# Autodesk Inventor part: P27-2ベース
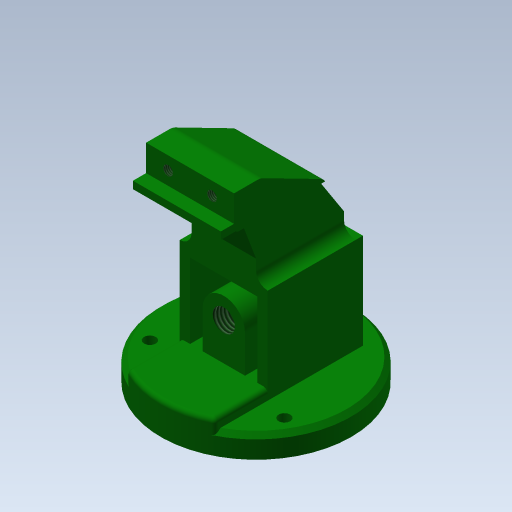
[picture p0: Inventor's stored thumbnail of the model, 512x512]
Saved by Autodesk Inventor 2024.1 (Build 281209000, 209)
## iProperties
Created: 2008-07
Part Number: P27-2ベース
Document SubType Name: Modeling
Designer: y-shimohigashi
Density: 1 g/cm^3
Stock Number: P24-2ベース
Material: 一般
Appearance: 濃い緑
Author: y-shimohigashi
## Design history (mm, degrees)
sketch "スケッチ2"
  geometry: C1 r 65 at (0, 0); 1 further point
  constraints: 1 centre point, 1 coincident
  dimensions: "d0" = 130 diameter of C1
extrude "押し出し1" new body sketch "スケッチ2" distance "d1" = 15; taper "d2" = 0 deg
sketch "スケッチ3"
  geometry: L1 (-65, 15)-(65, 15) reference; L2 (43, 15)-(43, 80); L3 (43, 80)-(38, 80); L4 (38, 80)-(38, 93); L5 (38, 93)-(16, 127); L6 (16, 127)-(-27, 149); L7 (-27, 149)-(-45, 149); L8 (-45, 149)-(-45, 131); L9 (-45, 131)-(-54, 131); L10 (-54, 131)-(-54, 126); L11 (-54, 126)-(-44, 126); L12 (-44, 126)-(-31, 119); L13 (-31, 119)-(-22, 95); L14 (-22, 95)-(-22, 15); L15 (-22, 15)-(43, 15); 1 further point
  constraints: 28 end point, 6 parallel, 3 perpendicular, 2 point on line, 1 collinear
  dimensions: "d3" = 43 distance from line of L2 point (0, 0); "d4" = 65 distance of L2.start L2.end; "d5" = 13 distance of L3.end L4.end; "d6" = 34 vertical distance of L4.end L5.end; "d7" = 22 vertical distance of L5.end L6.end; "d8" = 5 distance of L2.end L3.end; "d9" = 22 horizontal distance of L4.end L5.end; "d10" = 43 horizontal distance of L5.end L6.end; "d11" = 18 distance of L6.end L7.end; "d12" = 9 distance of L8.end L9.end; "d13" = 18 distance of L7.end L8.end; "d14" = 5 distance of L9.end L10.end; "d15" = 10 distance of L10.end L11.end; "d16" = 24 vertical distance of L12.end L13.end; "d17" = 80 distance of L13.end L14.end; "d18" = 65 distance between parallel lines of L2 L14; "d19" = 13 horizontal distance of L11.end L12.end
extrude "押し出し2" join sketch "スケッチ3" stored distance "d20" = 60; taper "d21" = 0 deg
sketch "スケッチ4"
  geometry: L1 (0, 0)-(60, 0) reference; L2 (60, 0)-(52, 0); L3 (52, 0)-(52, -45); L4 (52, -45)-(60, -45); L5 (60, -45)-(60, 0); L6 (0, 0)-(8, 0); L7 (8, 0)-(8, -45); L8 (8, -45)-(0, -45); L9 (0, -45)-(0, 0)
  constraints: 16 end point, 4 parallel, 2 collinear, 2 horizontal, 2 perpendicular
  dimensions: "d22" = 8 distance of L3.end L4.end; "d23" = 45 distance of L4.end L1.end
extrude "押し出し3" cut sketch "スケッチ4" extent not by distance; stored distance "d24" = 60; taper "d25" = 0 deg
sketch "スケッチ5"
  geometry: L1 (60, -65)-(60, 0) reference; L2 (0, 0)-(60, 0) reference; L3 (0, 0)-(0, -65) reference; L4 (0, -65)-(60, -65) reference; L5 (53, -58)-(53, -7); L6 (53, -7)-(7, -7); L7 (7, -7)-(7, -58); L8 (7, -58)-(53, -58); L9 (44.5, -7)-(44.5, -32.5); L10 (15.5, -32.5)-(15.5, -7); A1 r 14.5 centre (30, -32.5) between (15.5, -32.5) and (44.5, -32.5); 2 further points
  constraints: 12 end point, 2 midpoint, 2 perpendicular, 2 point on circle, 2 point on line, 2 tangent, 1 centre point, 1 horizontal alignment, 1 vertical alignment, 3 other
  dimensions: "d26" = 7 distance between parallel lines of L3 L7; "d27" = 8.5 distance between parallel lines of L7 L10
extrude "押し出し4" cut sketch "スケッチ5" extent not by distance; stored distance "d28" = 60; taper "d29" = 0 deg
hole "穴1" diameter "d32" = 15.294; stored, may be unused: countersink angle "d36" = 90 deg, drill point angle "d38" = 118 deg; dims "d30" = 10, "d31" = 10, "d33" = 6, "d34" = 4, "d35" = 2, "d37" = 8
sketch "スケッチ6"
  geometry: L1 (30, -22)-(-30, -22) reference; L2 (-30, -22)-(-30, -57.663); L3 (30, -22)-(30, -57.663); A1 r 65 centre (0, 0) between (-30, -57.663) and (30, -57.663) reference; A2 r 65 centre (0, 0) between (-30, -57.663) and (30, -57.663)
  constraints: 4 end point, 4 point on circle, 1 centre point, 1 concentric, 1 parallel, 1 perpendicular
extrude "押し出し5" join sketch "スケッチ6" stored distance "d39" = 60; taper "d40" = 0 deg
sketch "スケッチ7" dims "d41" = 106
  geometry: 3 further points
  constraints: 2 vertical alignment, 1 coincident, 2 other
hole "穴2" sketch "スケッチ7" diameter "d42" = 8; stored, may be unused: countersink angle "d46" = 90 deg, drill point angle "d48" = 118 deg; dims "d43" = 6, "d44" = 4, "d45" = 2, "d47" = 8
pattern_circular "放射状パターン1" dims angle "d50" = 360 deg
sketch "スケッチ8"
  geometry: L1 (30, -178.8)-(30, 29.8) reference; L2 (60, -18)-(60, 0) reference; 3 further points
  constraints: 1 horizontal alignment, 1 midpoint, 1 symmetric about line
  dimensions: "d53" = 30 distance of point (15, -9) point (45, -9)
hole "穴3" sketch "スケッチ8" diameter "d54" = 6.647; stored, may be unused: countersink angle "d58" = 90 deg, drill point angle "d60" = 118 deg; dims "d55" = 6, "d56" = 4, "d57" = 2, "d59" = 8
fillet "フィレット1" dims "d52" = 8
fillet "フィレット2" dims "d61" = 8
fillet "フィレット3" dims "d62" = 3
chamfer "面取り1" distance "d63" = 3; stored, may be unused: second distance "d64" = 2, angle "d65" = 45 deg
node "ソリッド1"
node "ソリッド ボディ"
node "サーフェス ボディ"
node "投影ループ1"
